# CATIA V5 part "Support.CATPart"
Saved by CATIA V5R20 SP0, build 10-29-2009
Part number: Support
Bounding box of the stored display mesh (mm): x -8 to 6, y -3 to 27, z -2.65 to 6.597
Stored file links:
  D:\Dropbox\IAO_2012\IAO_2012_746_mderemetz\IAO_2012_746_mderemetz_Catia\Support.CATPart
  D:\Dropbox\IAO_2012\IAO_2012_746_mderemetz\IAO_2012_746_mderemetz_Catia\mderemetz.CATProduct
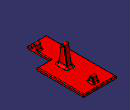
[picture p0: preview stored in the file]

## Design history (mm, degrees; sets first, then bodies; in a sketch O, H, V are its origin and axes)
External parameters (linked from other documents)
  External.AC = 3 mm
  External.Epaisseur = 1 mm
Set1
  Plane1 "Plan_Ref": linked copy from another document
  Point1 "A": linked copy from another document
  Point2 "F": linked copy from another document
  Point3 "G": linked copy from another document
Body1 (main body)
  Sketch1 on Plane1, origin (0, 0, 0), H (0, 1, 0), V (0, 0, 1)
    construction line L1 (12, 5.85) -> (12, -1.65)
    point P1 (12, 5.85)
    point P2 (12, -1.65)
    line L2 (12.74, 5.9723) -> (14, -1.65)
    line L3 (10, -1.65) -> (11.26, 5.9723)
    arc A1 centre (12, 5.85) radius 0.75 from (11.26, 5.9723) to (12.74, 5.9723) cw
    line L4 (10, -1.65) -> (14, -1.65)
    reference projected point E1 (12, 5.85) from Point1
    reference projected point E2 (12, 5.85) from Point1
    construction line L5 (24, 0) -> (24, -1.65)
    point P7 (24, 0)
    point P8 (24, -1.65)
    line L6 (24.7213, 0.2055) -> (25.25, -1.65)
    line L7 (22.75, -1.65) -> (23.2787, 0.2055)
    arc A2 centre (24, 0) radius 0.75 from (23.2787, 0.2055) to (24.7213, 0.2055) cw
    line L8 (22.75, -1.65) -> (25.25, -1.65)
    reference projected point E3 (24, 0) from Point2
    construction line L9 (0, 0) -> (0, -1.65)
    point P13 (0, 0)
    point P14 (0, -1.65)
    line L10 (0.7213, 0.2055) -> (1.25, -1.65)
    line L11 (-1.25, -1.65) -> (-0.7213, 0.2055)
    arc A3 centre (0, 0) radius 0.75 from (-0.7213, 0.2055) to (0.7213, 0.2055) cw
    line L12 (-1.25, -1.65) -> (1.25, -1.65)
    reference projected point E4 (0, 0) from Point3
    length L4 = 4 {= 4*External.AC /3}
    radius A1 = 0.75 {= 0.75*External.AC /3}
    distance E2 L4 = 7.5 {= 2.5*External.AC}
    radius A2 = 0.75 {= 0.75*External.AC /3}
    length L8 = 2.5 {= 2.5*External.AC /3}
    length L5 = 1.65 {= (2.5-1.95)*External.AC}
    radius A3 = 0.75 {= 0.75*External.AC /3}
    length L12 = 2.5 {= 2.5*External.AC /3}
    length L9 = 1.65 {= (2.5-1.95)*External.AC}
    vertical: L1 V, L5 V, L9 V
    tangency: A1 L2, A1 L3, A2 L6, A2 L7, A3 L10, A3 L11
    horizontal: L4 H, L8 H, L12 H
    midpoint: P2 L4, P8 L8, P14 L12
    coincidence: P1 E1, P7 E3, P13 E4
  Pad1: profile Sketch1, direction (-1, 0, 0), length 2 {= 2*External.AC /3}
  Sketch2 on face of Pad1 from Sketch1.L4, origin (0, 0, -1.65), H (1, 0, 0), V (0, -1, 0)
    line L1 (-8, 3) -> (6, 3)
    line L2 (6, 3) -> (6, -27)
    line L3 (6, -27) -> (-8, -27)
    line L4 (-8, -27) -> (-8, 3)
    reference projected line E1 (-2, -10) -> (-2, -14) from edge [end face of Pad1 | face of Pad1 from Sketch1.L4]
    reference intersected line E2 through (0, 0) direction (0, 1) from Plane1
    reference projected point E3 (0, -12) from Point1
    reference projected point E4 (0, -12) from Point1
    distance E1 L4 = 6 {= 2*External.AC}
    distance L2 E2 = 6 {= 2*External.AC}
    distance L1 E3 = 15 {= 5*External.AC}
    distance L3 E4 = 15 {= 5*External.AC}
    horizontal: L1 H, L3 H
    vertical: L2 V, L4 V
  Pad2: profile Sketch2, direction (0, 0, -1), length 1 {= External.AC /3}
  Fillet1: radius 0.2 {= 0.2*External.AC /3}, on edge [face of Pad1 from Sketch1.L3 | start face of Pad1]; edge [face of Pad1 from Sketch1.L7 | start face of Pad1]; edge [end face of Pad1 | face of Pad1 from Sketch1.L7]; edge [end face of Pad1 | face of Pad1 from Sketch1.L3]; edge [face of Pad1 from Sketch1.L11 | start face of Pad1]; edge [end face of Pad1 | face of Pad1 from Sketch1.L11]
  Sketch3 on start face of Pad2, origin (0, 0, -1.65), H (1, 0, 0), V (0, 1, 0)
    line L1 (6, -3) -> (0, -3)
    line L2 (0, -3) -> (0, 7)
    line L3 (0, 7) -> (6, 7)
    line L4 (6, 7) -> (6, -3)
    reference projected line E1 (6, -3) -> (-8, -3) from edge [start face of Pad2 | face of Pad2 from Sketch2.L1]
    reference projected line E2 (6, 27) -> (6, -3) from edge [start face of Pad2 | face of Pad2 from Sketch2.L2]
    distance L3 L1 = 10 {= 10*External.AC /3}
    horizontal: L1 H, L3 H
    vertical: L2 V, L4 V
    coincidence: V L2, E1 L1, L4 E2
  Pocket1: profile Sketch3, direction (0, 0, -1), through (limit type 3)
  Sketch4 on face of Pocket1, origin (0, 0, 0), H (0, 1, 0), V (0, 0, 1)
    circle A1 centre (0, 0) radius 0.25
    point P1 (0, 0)
    reference projected point E1 (0, 0) from Point3
    circle A2 centre (24, 0) radius 0.25
    point P2 (24, 0)
    circle A3 centre (12, 5.85) radius 0.25
    point P3 (12, 5.85)
    reference projected point E2 (12, 5.85) from Point1
    reference projected point E3 (24, 0) from Point2
    radius A1 = 0.25 {= 0.5*External.AC /6}
    radius A3 = 0.25 {= 0.5*External.AC /6}
    radius A2 = 0.25 {= 0.5*External.AC /6}
    coincidence: P1 E1, P3 E2, P2 E3
  Pad3: profile Sketch4, direction (1, 0, 0), length 1 {= External.Epaisseur}
  Fillet2: radius 1, on edge [start face of Pad2 | start face of Pad1]
  Fillet3: radius 0.5, on edge [start face of Pad2 | start face of Pad1]
  Fillet4: radius 0.5, on edge [face of Pad1 from Sketch1.L11 | start face of Pad2]
  Fillet5: radius 0.3, on edge [start face of Pad2 | face of Pad2 from Sketch2.L2]; edge [start face of Pad2 | face of Pocket1 from Sketch3.L3]; edge [start face of Pad2 | face of Pocket1] (x2); edge [start face of Pad2 | face of Pad2 from Sketch2.L1]; edge [start face of Pad2 | face of Pad2 from Sketch2.L4]; edge [start face of Pad2 | face of Pad2 from Sketch2.L3]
